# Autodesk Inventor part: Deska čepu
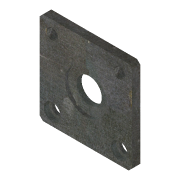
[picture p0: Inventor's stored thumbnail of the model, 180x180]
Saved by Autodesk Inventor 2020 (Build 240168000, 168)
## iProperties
Created: 2025-03
Part Number: Deska čepu
Material: Ocel
Document SubType Name: Modeling
Designer: doma
Density: 7.85 g/cm^3
Appearance: Plech
Mass: 813.582 g
Surface Area: 288.942 cm^2
Volume: 103.641 cm^3
Author: doma
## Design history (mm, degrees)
sketch "Náčrt1"
  geometry: C1 r 75 at (0, 0); C2 r 15 at (0, 0); 1 further point
  constraints: 2 centre point, 2 coincident
  dimensions: "d0" = 150 diameter of C1; "d1" = 30 diameter of C2
extrude "Vysunutí1" new body sketch "Náčrt1" distance "d2" = 10; taper "d3" = 0 deg
sketch "Náčrt2"
  geometry: C1 r 15 at (0, 0) reference; C2 r 25 at (0, 0); 1 further point
  constraints: 1 centre point, 1 coincident
  dimensions: "d4" = 50 diameter of C2
extrude "Vysunutí2" cut sketch "Náčrt2" distance "d5" = 4; taper "d6" = 0 deg
sketch "Náčrt3"
  geometry: L1 (0, 0)-(0, 55); L2 (0, 55)-(-55, 55); L3 (0, 55)-(55, 55); L4 (55, 55)-(55, -75); L5 (55, -75)-(128.19, -46.232); L6 (128.19, -46.232)-(119.784, 89.523); L7 (119.784, 89.523)-(-55, 102.972); L8 (-55, 102.972)-(-150.886, 23.957); L9 (-55, 55)-(-55, -92.401); L10 (-55, -92.401)-(-150.886, 23.957); L11 (55, -55)-(-55, -55); L12 (55, -75)-(-55, -92.401)
  constraints: 24 end point, 3 perpendicular, 2 point on line, 2 vertical, 1 horizontal
  dimensions: "d8" = 55 distance of L1.start L1.end; "d9" = 55 distance of L1.end L2.end; "d10" = 55 distance of L1.end L3.end; "d13" = 55 distance from line of L1.start L11
extrude "Vysunutí3" cut sketch "Náčrt3" extent not by distance; stored distance "d11" = 0; taper "d12" = 0 deg
sketch "Náčrt4"
  geometry: L1 (50.99, 55)-(-50.99, 55) reference; L2 (-55, 50.99)-(-55, -50.99) reference; 5 further points
  constraints: 1 horizontal, 1 vertical, 3 other
  dimensions: "d14" = 15 distance from line of L1 point (-40, 40); "d15" = 15 distance from line of L2 point (-40, 40); "d18" = 80 distance of point (-40, 40) point (40, 40); "d21" = 80 distance of point (-40, 40) point (-40, -40)
hole "Díra1" sketch "Náčrt4" at (-40, 40), (40, 40), (-40, -40), (40, -40) diameter "d24" = 13.5; stored, may be unused: countersink angle "d28" = 90 deg, drill point angle "d30" = 118 deg; dims "d25" = 6, "d26" = 4, "d27" = 2, "d29" = 8
sketch "Náčrt5"
  geometry: C1 r 6.75 at (-40, -40) reference; C2 r 10 at (-40, -40); C3 r 6.75 at (40, -40) reference; C4 r 10 at (40, -40); 1 further point
  constraints: 2 centre point, 2 coincident
  dimensions: "d31" = 20 diameter of C2; "d32" = 20 diameter of C4
extrude "Vysunutí4" cut sketch "Náčrt5" distance "d33" = 6; taper "d34" = 0 deg
fillet "Zaoblení1" dims "d35" = 0.2
chamfer "Zkosení1" distance "d36" = 1; stored, may be unused: second distance "d37" = 2, angle "d38" = 45 deg
node "Těleso1"
